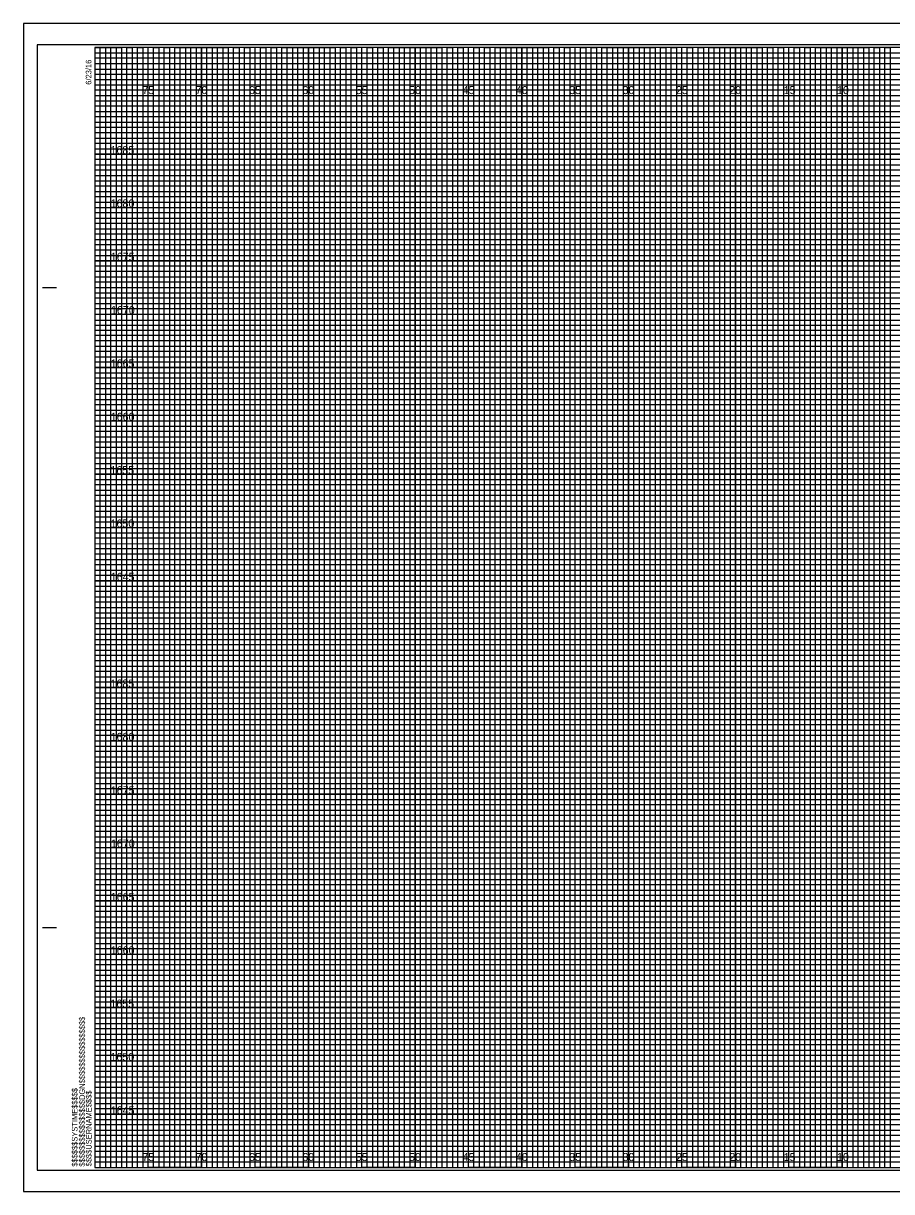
# Model space of a CAD drawing. Extents: x -7 to 162, y -2 to 217.
# Drawn here: x -6.7 to 74.6, y 107.7 to 217.2 of the extents above; entities that cross this region are included whole.
import ezdxf

# ---------------------------------------------------------------- set-up
doc = ezdxf.new("R2010")
doc.units = 0
for name, color, linetype in [('Prop XS Gore Control Minimum', 7, 'Continuous'), ('Raster_Level_0', 7, 'Continuous'), ('Scratch_Level_3', 7, 'Continuous'), ('Sheet Cross Section CELL', 7, 'Continuous'), ('Sheet Cross Section Grid Middle CELL', 7, 'Continuous'), ('Sheet Cross Section Grid Minor 1 CELL', 7, 'Continuous'), ('Sheet Cross Section Grid Minor 2 CELL', 7, 'Continuous'), ('Sheet Cutting Line CELL', 7, 'Continuous'), ('Sheet DOT Grid CELL', 7, 'Continuous'), ('Sheet Plot Border Inside CELL', 7, 'Continuous'), ('Sheet Plot Border Outside CELL', 7, 'Continuous')]:
    doc.layers.add(name, color=color, linetype=linetype)

msp = doc.modelspace()

# ---------------------------------------------------------------- linework, layer by layer
at = {"layer": 'Prop XS Gore Control Minimum'}
for p, q in [((5, 215), (0, 215)), ((5, 110), (5, 215)), ((15, 215), (10, 215)), ((10, 215), (10, 110)), ((15, 110), (15, 215)), ((25, 215), (20, 215)), ((20, 215), (20, 110)), ((25, 110), (25, 215)), ((35, 215), (30, 215)), ((30, 215), (30, 110)), ((35, 110), (35, 215)), ((45, 215), (40, 215)), ((40, 215), (40, 110)), ((45, 110), (45, 215)), ((55, 215), (50, 215)), ((50, 215), (50, 110)), ((55, 110), (55, 215)), ((65, 215), (60, 215)), ((60, 215), (60, 110)), ((65, 110), (65, 215)), ((75, 215), (70, 215)), ((70, 215), (70, 110)), ((10, 110), (5, 110)), ((20, 110), (15, 110)), ((30, 110), (25, 110)), ((40, 110), (35, 110)), ((50, 110), (45, 110)), ((60, 110), (55, 110)), ((70, 110), (65, 110))]:
    msp.add_line(p, q, dxfattribs=at)
for points in [[(0, 210), (160, 210), (160, 205), (0, 205)], [(0, 200), (160, 200), (160, 195), (0, 195)], [(0, 190), (160, 190), (160, 185), (0, 185)], [(0, 180), (160, 180), (160, 175), (0, 175)], [(0, 170), (160, 170), (160, 165), (0, 165)], [(0, 160), (160, 160), (160, 155), (0, 155)], [(0, 150), (160, 150), (160, 145), (0, 145)], [(0, 140), (160, 140), (160, 135), (0, 135)], [(0, 130), (160, 130), (160, 125), (0, 125)], [(0, 120), (160, 120), (160, 115), (0, 115)]]:
    msp.add_lwpolyline(points, dxfattribs=at)
at = {"layer": 'Sheet Cross Section CELL'}
for p, q in [((-4.9, 192.5), (-3.65, 192.5)), ((-4.85, 192.5), (-3.6, 192.5)), ((-4.9, 132.5), (-3.65, 132.5)), ((-4.85, 132.5), (-3.6, 132.5)), ((0, 110), (0, 110)), ((0, 110), (0, 110)), ((0, 110), (0, 110)), ((0, 110), (0, 110)), ((0, 110), (0, 110)), ((0, 110), (0, 110)), ((0, 110), (0, 110))]:
    msp.add_line(p, q, dxfattribs=at)
msp.add_lwpolyline([(160, 215), (0, 215), (0, 110), (160, 110)], close=True, dxfattribs=at)
at = {"layer": 'Sheet Cross Section Grid Middle CELL'}
for points in [[(0, 215), (2.5, 215), (2.5, 110), (7.5, 110), (7.5, 215), (12.5, 215), (12.5, 110), (17.5, 110), (17.5, 215), (22.5, 215), (22.5, 110), (27.5, 110), (27.5, 215), (32.5, 215), (32.5, 110), (37.5, 110), (37.5, 215), (42.5, 215), (42.5, 110), (47.5, 110), (47.5, 215), (52.5, 215), (52.5, 110), (57.5, 110), (57.5, 215), (62.5, 215), (62.5, 110), (67.5, 110), (67.5, 215), (72.5, 215), (72.5, 110), (77.5, 110)], [(0, 212.5), (137.5, 212.5)], [(0, 202.5), (160, 202.5), (160, 207.5), (0, 207.5)], [(0, 192.5), (160, 192.5), (160, 197.5), (0, 197.5)], [(0, 182.5), (160, 182.5), (160, 187.5), (0, 187.5)], [(0, 172.5), (160, 172.5), (160, 177.5), (0, 177.5)], [(0, 162.5), (160, 162.5), (160, 167.5), (0, 167.5)], [(0, 152.5), (160, 152.5), (160, 157.5), (0, 157.5)], [(0, 142.5), (160, 142.5), (160, 147.5), (0, 147.5)], [(0, 132.5), (160, 132.5), (160, 137.5), (0, 137.5)], [(0, 122.5), (160, 122.5), (160, 127.5), (0, 127.5)], [(0, 112.5), (160, 112.5), (160, 117.5), (0, 117.5)]]:
    msp.add_lwpolyline(points, dxfattribs=at)
at = {"layer": 'Sheet Cross Section Grid Minor 1 CELL'}
for p, q in [((0, 214.5), (130, 214.5)), ((130, 213.99), (0, 213.99)), ((0, 213.99), (0, 213.5)), ((0, 213.5), (130, 213.5)), ((130, 212.94), (0, 212.94)), ((0, 212.94), (0, 212)), ((0, 212), (160, 212))]:
    msp.add_line(p, q, dxfattribs=at)
for points in [[(0, 211.5), (135, 211.5), (160, 211.5), (160, 211), (0, 211)], [(0, 210.5), (160, 210.5), (160, 209.5), (0, 209.5)], [(0, 209), (160, 209), (160, 208.5), (0, 208.49)], [(0, 208), (160, 208), (160, 207), (0, 207)], [(0, 206.5), (160, 206.5), (160, 206), (0, 206)], [(0, 205.5), (160, 205.5), (160, 204.5), (0, 204.5)], [(0, 204), (160, 204), (160, 203.5), (0, 203.5)], [(0, 203), (160, 203), (160, 202), (0, 202)], [(0, 201.5), (160, 201.5), (160, 201), (0, 201)], [(0, 200.5), (160, 200.5), (160, 199.5), (0, 199.5)], [(0, 199), (160, 199), (160, 198.5), (0, 198.5)], [(0, 198), (160, 198), (160, 196.97), (160, 196.5), (160, 196), (0, 196)], [(0, 197), (160, 197), (160, 196.5), (0, 196.5)], [(0, 195.5), (160, 195.5), (160, 194.5), (0, 194.52)], [(0, 194.52), (160, 194.5), (160, 194), (0, 194)], [(0, 193.5), (160, 193.5), (160, 193), (0, 193)], [(0, 192), (160, 192), (160, 191.5), (0, 191.5)], [(0, 191), (160, 191), (160, 190.5), (0, 190.5)], [(-0.04, 189.44), (160, 189.44), (160, 188.94), (-0.04, 188.94)], [(0, 188.5), (160, 188.5), (160, 188), (0, 188)], [(0, 187), (160, 187), (160, 186.5), (0, 186.5)], [(0, 186), (160, 186), (160, 185.5), (0, 185.5)], [(0, 184.5), (160, 184.5), (160, 184), (0, 184)], [(0, 183.5), (160, 183.5), (160, 183), (0, 183)], [(0, 182), (160, 182), (160, 181.5), (0, 181.5)], [(0, 181), (160, 181), (160, 180.5), (0, 180.5)], [(0, 179.5), (160, 179.5), (160, 178.99), (0, 179)], [(0, 178.5), (160, 178.5), (160, 178), (0, 178)], [(0, 177), (160, 177), (160, 176.5), (0, 176.5)], [(0, 176), (160, 176), (160, 175.5), (0, 175.5)], [(0, 174.5), (160, 174.5), (160, 174), (0, 174)], [(0, 173.5), (160, 173.5), (160, 173), (0, 173)], [(0, 172), (160, 172), (160, 171.5), (0, 171.5)], [(0, 171), (160, 171), (160, 170.5), (0, 170.5)], [(0, 169.5), (160, 169.5), (160, 169), (0, 169)], [(0, 168.5), (160.03, 168.46), (160, 168), (0, 168)], [(0, 167), (160, 167), (160, 166.5), (0, 166.5)], [(0, 166), (160, 166), (160, 165.5), (0, 165.5)], [(0, 164.5), (160, 164.5), (160, 164), (0, 164)], [(0, 163.5), (160, 163.5), (160, 163), (0, 163)], [(0, 162), (160, 162), (160, 161.5), (0, 161.5)], [(0, 161), (160, 161), (160, 160.5), (0, 160.5)], [(0, 159.5), (160, 159.5), (160, 159), (0, 159)], [(0, 158.5), (160, 158.5), (160, 158), (0, 158)], [(0, 157), (160, 157), (160, 156.5), (0, 156.5)], [(0, 156), (160, 156), (160, 155.5), (0, 155.5)], [(0, 154.5), (160, 154.5), (160, 154), (0, 154)], [(0, 153.5), (160, 153.5), (160, 153), (0, 153)], [(0, 152), (160, 152), (160, 151.5), (0, 151.5)], [(0, 151), (160, 151), (160, 150.5), (0, 150.5)], [(0, 149.5), (160, 149.5), (160, 148.99), (0, 149)], [(0, 148.5), (160, 148.5), (160, 148), (0, 148)], [(0, 147), (160, 147), (160, 146.5), (0, 146.5)], [(0, 146), (160, 146), (160, 145.5), (0, 145.5)], [(0, 144.5), (160, 144.5), (160, 144), (0, 144)], [(0, 143.5), (160, 143.5), (160, 143), (0, 143)], [(0, 142), (160, 142), (160, 141.5), (0, 141.5)], [(0, 141), (160, 141), (160, 140.5), (0, 140.5)], [(0, 139.5), (160, 139.5), (160, 139), (0, 139)], [(0, 138.5), (160.03, 138.46), (160, 138), (0, 138)], [(0, 137), (160, 137), (160, 136.5), (0, 136.5)], [(0, 136), (160, 136), (160, 135.5), (0, 135.5)], [(0, 134.5), (160, 134.5), (160, 134), (0, 134)], [(0, 133.5), (160, 133.5), (160, 133), (0, 133)], [(0, 132), (160, 132), (160, 131.5), (0, 131.5)], [(0, 131), (160, 131), (160, 130.5), (0, 130.5)], [(0, 129.5), (160, 129.5), (160, 129), (0, 129)], [(0, 128.5), (160, 128.5), (160, 128), (0, 128)], [(0, 127), (160, 127), (160, 126.5), (0, 126.5)], [(0, 126), (160, 126), (160, 125.5), (0, 125.5)], [(0, 124.5), (160, 124.5), (160, 124), (0, 124)], [(0, 123.5), (160, 123.5), (160, 123), (0, 123)], [(0, 122), (160, 122), (160, 121.5), (0, 121.5)], [(0, 121), (160, 121), (160, 120.5), (0, 120.5)], [(0, 119.5), (160, 119.5), (160, 119), (0, 119)], [(0, 118.5), (160, 118.5), (160, 118), (0, 118)], [(0, 117), (160, 117), (160, 116.5), (0, 116.5)], [(0, 116), (160, 116), (160, 115.5), (0, 115.5)], [(0, 114.5), (160, 114.5), (160, 114), (0, 114)], [(0, 113.5), (160, 113.5), (160, 113), (0, 113)], [(0, 112), (160, 112), (160, 111.5), (0, 111.5)], [(0, 111), (160, 111), (160, 110.5), (0, 110.5)]]:
    msp.add_lwpolyline(points, dxfattribs=at)
at = {"layer": 'Sheet Cross Section Grid Minor 2 CELL'}
for points in [[(0, 110), (0.5, 110), (0.5, 215), (1, 215), (1, 110)], [(1, 110), (1.5, 110), (1.5, 215), (2, 215), (2, 110)], [(2.5, 110), (3, 110), (3, 215), (3.5, 215), (3.5, 110)], [(3.5, 110), (4, 110), (4, 215), (4.5, 215), (4.5, 110)], [(5, 110), (5.5, 110), (5.5, 215), (6, 215), (6, 110)], [(6, 110), (6.5, 110), (6.5, 215), (7, 215), (7, 110)], [(7.5, 110), (8, 110), (8, 215), (8.5, 215), (8.5, 110)], [(8.5, 110), (9, 110), (9, 215), (9.5, 215), (9.5, 110)], [(10, 110), (10.5, 110), (10.5, 215), (11, 215), (11, 110)], [(11, 110), (11.5, 110), (11.5, 215), (12, 215), (12, 110)], [(12.5, 110), (13, 110), (13, 215), (13.5, 215), (13.5, 110)], [(13.5, 110), (14, 110), (14, 215), (14.5, 215), (14.5, 110)], [(15, 110), (15.5, 110), (15.5, 215), (16, 215), (16, 110)], [(16, 110), (16.5, 110), (16.5, 215), (17, 215), (17, 110)], [(17.5, 110), (18, 110), (18, 215), (18.5, 215), (18.5, 110)], [(18.5, 110), (19, 110), (19, 215), (19.5, 215), (19.5, 110)], [(20, 110), (20.5, 110), (20.5, 215), (21, 215), (21, 110)], [(21, 110), (21.5, 110), (21.5, 215), (22, 215), (22, 110)], [(22.5, 110), (23, 110), (23, 215), (23.5, 215), (23.5, 110)], [(23.5, 110), (24, 110), (24, 215), (24.5, 215), (24.5, 110)], [(25, 110), (25.5, 110), (25.5, 215), (26, 215), (26, 110)], [(26, 110), (26.5, 110), (26.5, 215), (27, 215), (27, 110)], [(27.5, 110), (28, 110), (28, 215), (28.5, 215), (28.5, 110)], [(28.5, 110), (29, 110), (29, 215), (29.5, 215), (29.5, 110)], [(30, 110), (30.5, 110), (30.5, 215), (31, 215), (31, 110)], [(31, 110), (31.5, 110), (31.5, 215), (32, 215), (32, 110)], [(32.5, 110), (33, 110), (33, 215), (33.5, 215), (33.5, 110)], [(33.5, 110), (34, 110), (34, 215), (34.5, 215), (34.5, 110)], [(35, 110), (35.5, 110), (35.5, 215), (36, 215), (36, 110)], [(36, 110), (36.5, 110), (36.5, 215), (37, 215), (37, 110)], [(37.5, 110), (38, 110), (38, 215), (38.5, 215), (38.5, 110)], [(38.5, 110), (39, 110), (39, 215), (39.5, 215), (39.5, 110)], [(40, 110), (40.5, 110), (40.5, 215), (41, 215), (41, 110)], [(41, 110), (41.5, 110), (41.5, 215), (42, 215), (42, 110)], [(42.5, 110), (43, 110), (43, 215), (43.5, 215), (43.5, 110)], [(43.5, 110), (44, 110), (44, 215), (44.5, 215), (44.5, 110)], [(45, 110), (45.5, 110), (45.5, 215), (46, 215), (46, 110)], [(46, 110), (46.5, 110), (46.5, 215), (47, 215), (47, 110)], [(47.5, 110), (48, 110), (48, 215), (48.5, 215), (48.5, 110)], [(48.5, 110), (49, 110), (49, 215), (49.5, 215), (49.5, 110)], [(50, 110), (50.5, 110), (50.5, 215), (51, 215), (51, 110)], [(51, 110), (51.5, 110), (51.5, 215), (52, 215), (52, 110)], [(52.5, 110), (53, 110), (53, 215), (53.5, 215), (53.5, 110)], [(53.5, 110), (54, 110), (54, 215), (54.5, 215), (54.5, 110)], [(55, 110), (55.5, 110), (55.5, 215), (56, 215), (56, 110)], [(56, 110), (56.5, 110), (56.5, 215), (57, 215), (57, 110)], [(57.5, 110), (58, 110), (58, 215), (58.5, 215), (58.5, 110)], [(58.5, 110), (59, 110), (59, 215), (59.5, 215), (59.5, 110)], [(60, 110), (60.5, 110), (60.5, 215), (61, 215), (61, 110)], [(61, 110), (61.5, 110), (61.5, 215), (62, 215), (62, 110)], [(62.5, 110), (63, 110), (63, 215), (63.5, 215), (63.5, 110)], [(63.5, 110), (64, 110), (64, 215), (64.5, 215), (64.5, 110)], [(65, 110), (65.5, 110), (65.5, 215), (66, 215), (66, 110)], [(66, 110), (66.5, 110), (66.5, 215), (67, 215), (67, 110)], [(67.5, 110), (68, 110), (68, 215), (68.5, 215), (68.5, 110)], [(68.5, 110), (69, 110), (69, 215), (69.5, 215), (69.5, 110)], [(70, 110), (70.5, 110), (70.5, 215), (71, 215), (71, 110)], [(71, 110), (71.5, 110), (71.5, 215), (72, 215), (72, 110)], [(72.5, 110), (73, 110), (73, 215), (73.5, 215), (73.5, 110)], [(73.5, 110), (74, 110), (74, 215), (74.5, 215), (74.5, 110)]]:
    msp.add_lwpolyline(points, dxfattribs=at)
at = {"layer": 'Sheet Cutting Line CELL'}
for p, q in [((161.65, 217.25), (-6.7, 217.25)), ((-6.7, 217.25), (-6.7, 107.75)), ((-6.7, 107.75), (161.65, 107.75))]:
    msp.add_line(p, q, dxfattribs=at)
at = {"layer": 'Sheet DOT Grid CELL'}
for p, q in [((5, 110), (5, 215)), ((10, 110), (10, 215)), ((15, 110), (15, 215)), ((20, 110), (20, 215)), ((25, 110), (25, 215)), ((30, 110), (30, 215)), ((35, 110), (35, 215)), ((40, 110), (40, 215)), ((45, 110), (45, 215)), ((50, 110), (50, 215)), ((55, 110), (55, 215)), ((60, 110), (60, 215)), ((65, 110), (65, 215)), ((70, 110), (70, 215)), ((0, 210), (160, 210)), ((0, 205), (160, 205)), ((0, 200), (160, 200)), ((0, 195), (160, 195)), ((0, 190), (160, 190)), ((0, 185), (160, 185)), ((0, 180), (160, 180)), ((0, 175), (160, 175)), ((0, 170), (160, 170)), ((0, 165), (160, 165)), ((0, 160), (160, 160)), ((0, 155), (160, 155)), ((0, 150), (160, 150)), ((0, 145), (160, 145)), ((0, 140), (160, 140)), ((0, 135), (160, 135)), ((0, 130), (160, 130)), ((0, 125), (160, 125)), ((0, 120), (160, 120)), ((0, 115), (160, 115))]:
    msp.add_line(p, q, dxfattribs=at)
at = {"layer": 'Sheet Plot Border Inside CELL'}
msp.add_lwpolyline([(-5.4, 109.75), (161.2, 109.75), (161.2, 215.25), (-5.4, 215.25)], close=True, dxfattribs=at)
at = {"layer": 'Sheet Plot Border Outside CELL'}
msp.add_lwpolyline([(-6.7, 107.75), (161.65, 107.75), (161.65, 217.25), (-6.7, 217.25)], close=True, dxfattribs=at)

# ---------------------------------------------------------------- texts
at = {"layer": 'Raster_Level_0'}
for s, p in [('75', (4.44, 210.62)), ('70', (9.43, 210.62)), ('65', (14.44, 210.62)), ('60', (19.43, 210.62)), ('55', (24.44, 210.62)), ('50', (29.43, 210.62)), ('45', (34.44, 210.62)), ('40', (39.43, 210.62)), ('35', (44.44, 210.62)), ('30', (49.43, 210.62)), ('25', (54.44, 210.62)), ('20', (59.43, 210.62)), ('15', (64.53, 210.62)), ('10', (69.52, 210.62)), ('75', (4.44, 110.62)), ('70', (9.43, 110.62)), ('65', (14.44, 110.62)), ('60', (19.43, 110.62)), ('55', (24.44, 110.62)), ('50', (29.43, 110.62)), ('45', (34.44, 110.62)), ('40', (39.43, 110.62)), ('35', (44.44, 110.62)), ('30', (49.43, 110.62)), ('25', (54.44, 110.62)), ('20', (59.43, 110.62)), ('15', (64.53, 110.62)), ('10', (69.52, 110.62))]:
    msp.add_text(s, height=0.75, dxfattribs=at).set_placement(p)
at = {"layer": 'Scratch_Level_3'}
for s, p in [('1685', (1.46, 205)), ('1680', (1.47, 200)), ('1675', (1.49, 195)), ('1670', (1.5, 190)), ('1665', (1.48, 185)), ('1660', (1.48, 180)), ('1655', (1.45, 175)), ('1650', (1.46, 170)), ('1645', (1.48, 165)), ('1685', (1.46, 155)), ('1680', (1.47, 150)), ('1675', (1.49, 145)), ('1670', (1.5, 140)), ('1665', (1.48, 135)), ('1660', (1.48, 130)), ('1655', (1.45, 125)), ('1650', (1.46, 120)), ('1645', (1.48, 115))]:
    msp.add_text(s, height=0.75, dxfattribs=at).set_placement(p)
at = {"layer": 'Sheet Cross Section CELL'}
for s, p in [('6/23/16', (-0.33, 211.5)), ('$$$$$$$$$$$$$$$$DGN$$$$$$$$$$$$$$$$', (-0.94, 110.09)), ('$$$$$$SYSTIME$$$$$', (-1.63, 110.09)), ('$$$$USERNAME$$$$', (-0.31, 110.12))]:
    msp.add_text(s, height=0.525, rotation=90, dxfattribs=at).set_placement(p)

doc.saveas('drawing.dxf')
